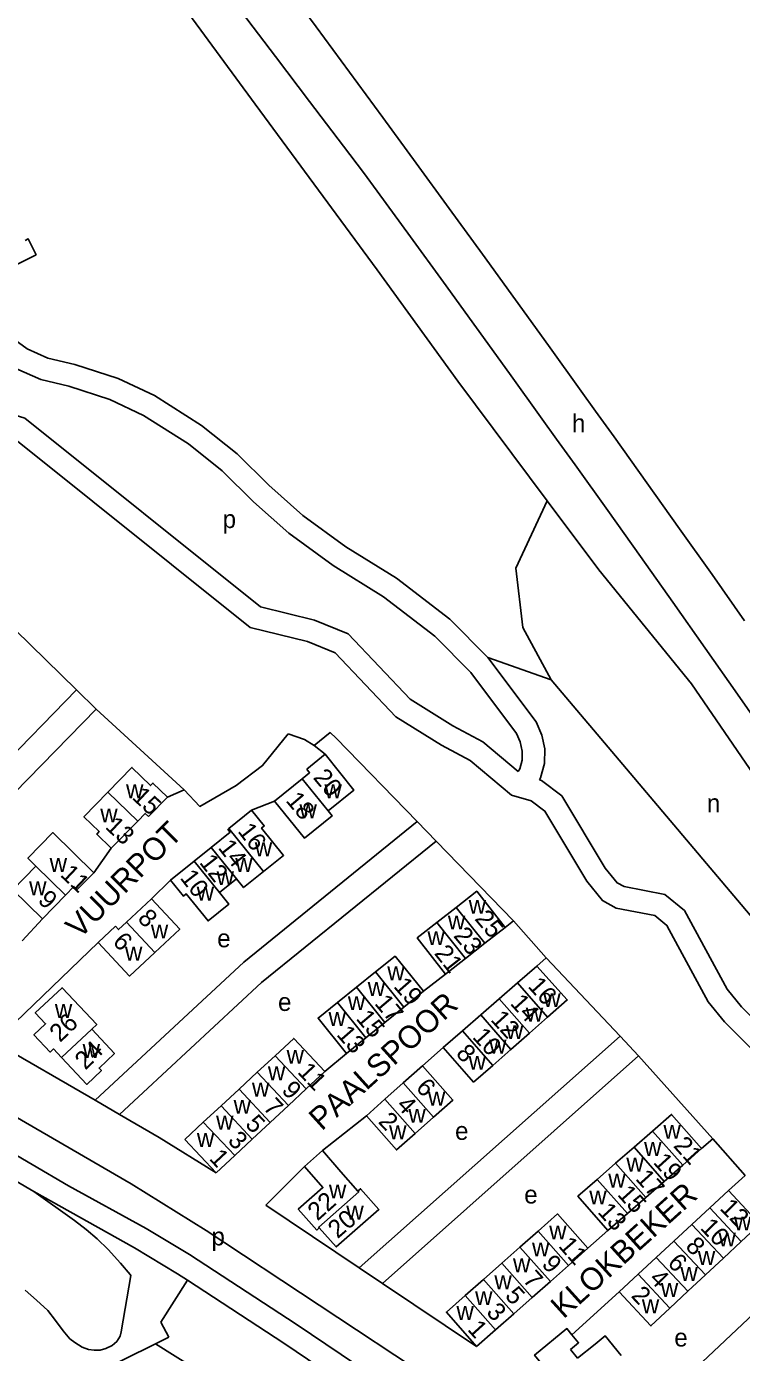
# Model space of a CAD drawing. Extents: x 159441 to 162086, y 388175 to 389787.
# Drawn here: x 161428.2 to 161586.8, y 389289.4 to 389583.7 of the extents above; entities that cross this region are included whole.
import ezdxf

# ---------------------------------------------------------------- set-up
doc = ezdxf.new("R2010")
doc.units = 0
for name, color, linetype in [('BLT_Basislijn', 7, 'Continuous'), ('BLT_Bebouwing', 7, 'Continuous'), ('BLT_Centroide', 7, 'Continuous'), ('BLT_Huisnummer', 7, 'Continuous'), ('BLT_Huisnummer_ tussenligend', 7, 'Continuous'), ('BLT_Onderverdeling_panden', 7, 'Continuous'), ('BLT_Straatnaam', 7, 'Continuous'), ('BLT_Vlakafsluiter', 7, 'Continuous')]:
    doc.layers.add(name, color=color, linetype=linetype)

msp = doc.modelspace()

# ---------------------------------------------------------------- linework, layer by layer
at = {"layer": 'BLT_Basislijn'}
for p, q in [((161383.9, 389379.42), (161439.23, 389436.44)), ((161443.62, 389432.16), (161439.23, 389436.44)), ((161443.62, 389432.16), (161463.1, 389414.22)), ((161486.17, 389426.67), (161489.82, 389425.44)), ((161491.95, 389424.06), (161494.43, 389422.14)), ((161459.41, 389412.61), (161463.1, 389414.22)), ((161478.09, 389409.72), (161483.16, 389411.76)), ((161519.05, 389402.87), (161514.85, 389407.19)), ((161536.2, 389385.19), (161519.05, 389402.87)), ((161443.08, 389395.85), (161446.94, 389401.27)), ((161455.9, 389390.05), (161460.13, 389394.19)), ((161427.19, 389380.73), (161431.71, 389385.62)), ((161536.2, 389385.19), (161534.34, 389383.72)), ((161536.2, 389385.19), (161543.45, 389376.98)), ((161421.08, 389358.27), (161444.06, 389380.35)), ((161516.21, 389369.53), (161521.13, 389373.34)), ((161501.97, 389308.16), (161559.82, 389359.6)), ((161563.93, 389355.23), (161559.82, 389359.6)), ((161494.31, 389351.71), (161499.17, 389355.75)), ((161507.11, 389304.7), (161563.93, 389355.23)), ((161520.62, 389357.04), (161516.01, 389353.01)), ((161443.36, 389345.36), (161448.79, 389342.21)), ((161448.79, 389342.21), (161457.6, 389337.11)), ((161503.56, 389341.9), (161493.84, 389334.19)), ((161580.41, 389336.8), (161587.55, 389328.63)), ((161489.81, 389330.62), (161481.24, 389322.1)), ((161587.55, 389328.63), (161583.88, 389325.3)), ((161481.24, 389322.1), (161501.97, 389308.16)), ((161557.15, 389316.42), (161552.71, 389312.5)), ((161501.97, 389308.16), (161507.11, 389304.7)), ((161457.93, 389296.13), (161463.86, 389305.42)), ((161507.11, 389304.7), (161527.98, 389290.67)), ((161559.63, 389302.82), (161549.16, 389293.32)), ((161456.75, 389291.27), (161491.3, 389269.76))]:
    msp.add_line(p, q, dxfattribs=at)
for points in [[(161543.69, 389478.37), (161523.86, 389504.93), (161505.95, 389529.67), (161478.86, 389566.44), (161457.19, 389596.01)], [(161485, 389593.68), (161492.42, 389583.62), (161499.82, 389573.54), (161507.21, 389563.46), (161514.58, 389553.36), (161521.94, 389543.26), (161529.28, 389533.14), (161536.61, 389523.01), (161543.92, 389512.88), (161551.22, 389502.73), (161554.39, 389498.31), (161558.51, 389492.57), (161565.77, 389482.39), (161573.01, 389472.2), (161580.24, 389462), (161587.44, 389451.78)], [(161475.82, 389586.9), (161483.4, 389576.97), (161490.96, 389567.04), (161498.51, 389557.1), (161502.92, 389551.28), (161505.98, 389547.09), (161513.33, 389537), (161520.66, 389526.89), (161527.98, 389516.78), (161535.28, 389506.65), (161542.57, 389496.52), (161545.74, 389492.1), (161549.84, 389486.37), (161557.1, 389476.21), (161564.33, 389466.04), (161571.54, 389455.86), (161578.73, 389445.66), (161585.9, 389435.44), (161593.05, 389425.21)], [(161427.86, 389536.18), (161428.54, 389536.51), (161430.3, 389532.99), (161421.26, 389528.53)], [(161530.5, 389443.58), (161522.03, 389452.09), (161510.21, 389461.22), (161498.99, 389468.19), (161489.49, 389475.11), (161481.93, 389481.84), (161474.86, 389488.78), (161466.99, 389495.13), (161456.52, 389501.73), (161448.47, 389505.52), (161438.87, 389508.66), (161432.92, 389510.04), (161428.28, 389512.12), (161419.52, 389518.47)], [(161537.21, 389418.33), (161537.56, 389418.92), (161538.1, 389420.8), (161538.12, 389422.8), (161537.68, 389424.86), (161536.85, 389426.77), (161526.71, 389440.3), (161518.71, 389448.33), (161507.35, 389457.11), (161496.2, 389464.04), (161486.35, 389471.21), (161478.52, 389478.19), (161471.53, 389485.04), (161464.07, 389491.06), (161454.11, 389497.34), (161446.62, 389500.86), (161437.52, 389503.84), (161431.31, 389505.28), (161425.76, 389507.77), (161421.81, 389510.63)], [(161537.21, 389418.33), (161529.36, 389424.91), (161522.71, 389428.48), (161513.29, 389434.38), (161499.5, 389448.87), (161492.04, 389451.92), (161480.04, 389454.84), (161427.81, 389496.7), (161417.81, 389499.83)], [(161589.54, 389356.14), (161583.02, 389362.73), (161579.4, 389367.2), (161570.22, 389384.16), (161567.55, 389386.32), (161558.99, 389388.01), (161555.9, 389389.68), (161552.43, 389393.96), (161543.15, 389409.51), (161540.12, 389411.79), (161535.71, 389413.06), (161526.54, 389420.75), (161520.2, 389424.16), (161510.11, 389430.47), (161496.62, 389444.64), (161490.49, 389447.15), (161477.78, 389450.24), (161425.41, 389492.21)], [(161544.52, 389438.64), (161538.25, 389450.28), (161536.73, 389463.42), (161543.69, 389478.37)], [(161864.11, 388992.72), (161862.26, 388996.22), (161834.62, 389043.66), (161820.58, 389066.73), (161794.96, 389108.1), (161778.03, 389134.85), (161748.78, 389180.87), (161736.01, 389200.14), (161730.36, 389208.82), (161706.15, 389245.56), (161679.72, 389284.71), (161666.51, 389304.75), (161627.77, 389361.67), (161610.82, 389386.7), (161592.22, 389413.57), (161575.68, 389437.79), (161555.14, 389463.04), (161543.69, 389478.37)], [(161439.23, 389436.44), (161422.15, 389453.11)], [(161541.93, 389416.47), (161542.19, 389416.9), (161543.1, 389420.07), (161543.13, 389423.31), (161542.46, 389426.39), (161541.21, 389429.3), (161530.5, 389443.58)], [(161819.53, 389045.68), (161815.48, 389052.86), (161784.08, 389105), (161747.27, 389163.43), (161708.15, 389220.33), (161663.36, 389280.15), (161636.73, 389321.37), (161599.17, 389374.01), (161561.24, 389418.87), (161544.52, 389438.64)], [(161389.22, 389376.43), (161443.62, 389432.16)], [(161463.1, 389414.22), (161466.63, 389410.56), (161474.67, 389415.22), (161480.53, 389419.61), (161486.17, 389426.67)], [(161491.95, 389424.06), (161489.82, 389425.44)], [(161514.85, 389407.19), (161496.86, 389425.73), (161495.53, 389426.95), (161491.95, 389424.06)], [(161665.94, 389267.22), (161644.27, 389297.16), (161632.06, 389317.53), (161628.84, 389320.63), (161616.45, 389326.78), (161614.95, 389328.05), (161612.91, 389331.22), (161603.71, 389347.88), (161598.07, 389353.27), (161593.31, 389359.44), (161586.75, 389366.07), (161583.57, 389369.99), (161574.14, 389387.43), (161569.73, 389390.99), (161560.7, 389392.77), (161559.16, 389393.6), (161556.54, 389396.83), (161546.94, 389412.91), (161542.39, 389416.34), (161541.93, 389416.47)], [(161443.36, 389345.36), (161476.39, 389376.03), (161514.85, 389407.19)], [(161448.79, 389342.21), (161480.32, 389371.49), (161519.05, 389402.87)], [(161543.45, 389376.98), (161541.34, 389375.11)], [(161559.82, 389359.6), (161543.45, 389376.98)], [(161421.08, 389358.27), (161443.36, 389345.36)], [(161580.41, 389336.8), (161563.93, 389355.23)], [(161411.85, 389349.75), (161451.41, 389326.83)], [(161437.49, 389326.37), (161405.15, 389345.27)], [(161429.8, 389325.08), (161400.53, 389342.18)], [(161457.6, 389337.11), (161470.24, 389329.22)], [(161577.92, 389334.61), (161580.41, 389336.8)], [(161429.8, 389325.08), (161438.83, 389318.69), (161441.42, 389316.65), (161443.82, 389314.56), (161446.24, 389312.21), (161449.02, 389309.2), (161451.15, 389306.66), (161451.31, 389306.44)], [(161429.8, 389325.08), (161452.09, 389312.58), (161461.65, 389306.86), (161463.86, 389305.42)], [(161437.49, 389326.37), (161454.67, 389316.87), (161464.3, 389311.1), (161488.01, 389295.63), (161511.38, 389279.86)], [(161451.41, 389326.83), (161468.04, 389316.44), (161518.16, 389283.27)], [(161557.27, 389269.87), (161573.01, 389282.52), (161603.38, 389311.15)], [(161427.9, 389303.23), (161430.39, 389300.98), (161432.88, 389298.66), (161434.6, 389296.49), (161436.31, 389294.17), (161437.77, 389292.43), (161438.87, 389291.56), (161440.52, 389290.58), (161441.92, 389290.05), (161443.16, 389289.88), (161444.51, 389289.91), (161445.77, 389290.23), (161447.17, 389290.89), (161448.18, 389291.8), (161448.9, 389292.97), (161449.18, 389293.93), (161451.31, 389306.44)], [(161463.86, 389305.42), (161485.25, 389291.46), (161506.5, 389277.12)], [(161457.93, 389296.13), (161459.75, 389292.75)], [(161459.75, 389292.75), (161456.75, 389291.27)], [(161456.75, 389291.27), (161436.02, 389281.03), (161437.12, 389278.67)]]:
    msp.add_lwpolyline(points, dxfattribs=at)
at = {"layer": 'BLT_Bebouwing'}
for p, q in [((161523.45, 389388.15), (161519.18, 389384.79)), ((161529.82, 389380.18), (161534.34, 389383.72)), ((161525.55, 389376.82), (161529.82, 389380.18)), ((161521.13, 389373.34), (161525.55, 389376.82)), ((161541.34, 389375.11), (161537.09, 389371.4)), ((161505.59, 389373.84), (161501.36, 389370.44)), ((161537.09, 389371.4), (161533.03, 389367.87)), ((161533.03, 389367.87), (161528.94, 389364.3)), ((161528.94, 389364.3), (161524.87, 389360.75)), ((161539.71, 389360.23), (161543.75, 389363.77)), ((161507.67, 389362.62), (161503.46, 389359.22)), ((161535.63, 389356.64), (161539.71, 389360.23)), ((161483.3, 389355.21), (161479.36, 389351.56)), ((161531.57, 389353.09), (161535.63, 389356.64)), ((161516.01, 389353.01), (161511.73, 389349.19)), ((161511.73, 389349.19), (161507.68, 389345.58)), ((161475.31, 389347.8), (161471.33, 389344.12)), ((161507.68, 389345.58), (161503.56, 389341.9)), ((161467.38, 389340.45), (161471.33, 389344.12)), ((161486.25, 389344.19), (161482.21, 389340.42)), ((161467.38, 389340.45), (161463.27, 389336.64)), ((161514.38, 389338), (161518.45, 389341.58)), ((161463.27, 389336.64), (161470.24, 389329.22)), ((161474.34, 389333.07), (161478.25, 389336.72)), ((161567.05, 389338.52), (161562.92, 389334.92)), ((161562.92, 389334.92), (161558.82, 389331.35)), ((161573.74, 389330.95), (161577.92, 389334.61)), ((161558.82, 389331.35), (161554.74, 389327.79)), ((161569.63, 389327.35), (161573.74, 389330.95)), ((161565.54, 389323.76), (161569.63, 389327.35)), ((161583.88, 389325.3), (161579.73, 389321.45)), ((161561.46, 389320.19), (161565.54, 389323.76)), ((161557.15, 389316.42), (161561.46, 389320.19)), ((161579.73, 389321.45), (161575.78, 389317.79)), ((161541.68, 389316.32), (161537.63, 389312.74)), ((161575.78, 389317.79), (161571.77, 389314.07)), ((161571.77, 389314.07), (161567.85, 389310.43)), ((161582.77, 389310.33), (161586.7, 389314.01)), ((161537.63, 389312.74), (161533.6, 389309.18)), ((161548.42, 389308.71), (161552.71, 389312.5)), ((161567.85, 389310.43), (161563.87, 389306.74)), ((161578.78, 389306.6), (161582.77, 389310.33)), ((161533.6, 389309.18), (161529.51, 389305.58)), ((161544.36, 389305.13), (161548.42, 389308.71)), ((161529.51, 389305.58), (161525.47, 389302.01)), ((161540.33, 389301.57), (161544.36, 389305.13)), ((161563.87, 389306.74), (161559.63, 389302.82)), ((161574.87, 389302.94), (161578.78, 389306.6)), ((161536.25, 389297.97), (161540.33, 389301.57)), ((161570.9, 389299.23), (161574.87, 389302.94)), ((161532.21, 389294.41), (161536.25, 389297.97)), ((161527.98, 389290.67), (161532.21, 389294.41)), ((161550.39, 389288.08), (161548.81, 389290))]:
    msp.add_line(p, q, dxfattribs=at)
for points in [[(161494.43, 389422.14), (161490.32, 389418.82)], [(161495.06, 389409.55), (161500.78, 389414.19), (161494.43, 389422.14)], [(161459.41, 389412.61), (161456.2, 389415.75), (161455.66, 389415.19), (161451.55, 389419.2), (161446.22, 389413.74)], [(161489.29, 389416.7), (161483.16, 389411.76)], [(161490.32, 389418.82), (161490.95, 389418.04), (161489.29, 389416.7)], [(161446.22, 389413.74), (161440.89, 389408.28), (161444.27, 389404.98), (161443.73, 389404.43), (161446.94, 389401.27)], [(161455.21, 389408.32), (161459.41, 389412.61)], [(161483.16, 389411.76), (161489.8, 389403.52), (161495.95, 389408.45), (161495.06, 389409.55)], [(161446.94, 389401.27), (161452.83, 389407.28)], [(161452.83, 389407.28), (161454.51, 389409), (161455.21, 389408.32)], [(161478.09, 389409.72), (161473.03, 389405.63)], [(161480.74, 389396.13), (161485.17, 389399.7), (161480.29, 389405.74), (161480.9, 389406.24), (161478.09, 389409.72)], [(161443.08, 389395.85), (161433.99, 389404.74), (161428.47, 389399.08), (161430.26, 389397.32)], [(161473.03, 389405.63), (161472.83, 389405.47), (161473.35, 389404.85), (161469.13, 389401.45)], [(161469.13, 389401.45), (161465.36, 389398.41)], [(161465.36, 389398.41), (161460.13, 389394.19)], [(161430.26, 389397.32), (161425.12, 389392.05), (161431.71, 389385.62)], [(161439.42, 389392.09), (161443.08, 389395.85)], [(161474.76, 389394.52), (161476.32, 389392.56), (161480.74, 389396.13)], [(161436.84, 389390.89), (161438.69, 389392.79), (161439.42, 389392.09)], [(161460.13, 389394.19), (161462.96, 389390.68), (161463.55, 389391.17), (161468.44, 389385.16), (161473.07, 389388.89), (161470.99, 389391.47)], [(161470.99, 389391.47), (161474.76, 389394.52)], [(161431.71, 389385.62), (161436.84, 389390.89)], [(161455.9, 389390.05), (161450.33, 389384.84)], [(161456.59, 389378.11), (161462.17, 389383.34), (161455.9, 389390.05)], [(161534.34, 389383.72), (161528.03, 389391.75), (161523.45, 389388.15)], [(161447.9, 389383.96), (161444.06, 389380.35)], [(161450.33, 389384.84), (161448.59, 389383.22), (161447.9, 389383.96)], [(161519.18, 389384.79), (161514.82, 389381.37), (161521.13, 389373.34)], [(161444.06, 389380.35), (161450.99, 389372.89), (161456.59, 389378.11)], [(161505.59, 389373.84), (161509.92, 389377.32), (161516.21, 389369.53)], [(161543.75, 389363.77), (161548.12, 389367.61), (161541.34, 389375.11)], [(161442.63, 389361.1), (161443.73, 389362.13), (161436.05, 389370.33), (161430.11, 389364.76), (161432.4, 389362.31), (161429.82, 389359.89), (161433.42, 389356.04), (161434.17, 389356.74), (161435.95, 389354.84)], [(161497.15, 389367.05), (161501.36, 389370.44)], [(161516.21, 389369.53), (161511.89, 389366.03)], [(161497.15, 389367.05), (161492.84, 389363.58), (161499.17, 389355.75)], [(161507.67, 389362.62), (161511.89, 389366.03)], [(161435.95, 389354.84), (161441.54, 389348.87), (161444.77, 389351.95), (161444.26, 389352.49), (161447.67, 389355.69), (161442.63, 389361.1)], [(161524.87, 389360.75), (161520.62, 389357.04)], [(161483.3, 389355.21), (161487.44, 389359.06), (161494.31, 389351.71)], [(161499.17, 389355.75), (161503.46, 389359.22)], [(161520.62, 389357.04), (161527.35, 389349.38), (161531.57, 389353.09)], [(161475.31, 389347.8), (161479.36, 389351.56)], [(161494.31, 389351.71), (161490.18, 389347.86)], [(161518.45, 389341.58), (161522.74, 389345.37), (161516.01, 389353.01)], [(161486.25, 389344.19), (161490.18, 389347.86)], [(161478.25, 389336.72), (161482.21, 389340.42)], [(161503.56, 389341.9), (161510.22, 389334.34), (161514.38, 389338)], [(161577.92, 389334.61), (161571.27, 389342.2), (161567.05, 389338.52)], [(161493.84, 389334.19), (161489.81, 389330.62)], [(161501.69, 389325.2), (161497.92, 389329.48), (161493.84, 389334.19)], [(161470.24, 389329.22), (161474.34, 389333.07)], [(161489.81, 389330.62), (161493.9, 389325.95), (161488.45, 389321.17), (161492.54, 389316.55), (161493.11, 389317.05)], [(161554.74, 389327.79), (161550.46, 389324.06), (161557.15, 389316.42)], [(161493.11, 389317.05), (161496.87, 389312.78), (161506.33, 389321.12), (161502.28, 389325.72), (161501.69, 389325.2)], [(161586.7, 389314.01), (161590.83, 389317.87), (161583.88, 389325.3)], [(161552.71, 389312.5), (161545.98, 389320.11), (161541.68, 389316.32)], [(161525.47, 389302.01), (161521.32, 389298.35), (161527.98, 389290.67)], [(161559.63, 389302.82), (161566.68, 389295.28), (161570.9, 389299.23)], [(161549.16, 389293.32), (161548.05, 389294.66), (161540.88, 389288.78), (161542.28, 389287.08)], [(161548.81, 389290), (161550.64, 389291.51), (161549.16, 389293.32)], [(161560.06, 389288.73), (161556.49, 389293.07), (161554.27, 389291.25), (161550.39, 389288.08)]]:
    msp.add_lwpolyline(points, dxfattribs=at)
at = {"layer": 'BLT_Onderverdeling_panden'}
for p, q in [((161523.45, 389388.15), (161529.82, 389380.18)), ((161519.18, 389384.79), (161525.55, 389376.82)), ((161511.89, 389366.03), (161505.59, 389373.84)), ((161501.36, 389370.44), (161507.67, 389362.62)), ((161537.09, 389371.4), (161543.75, 389363.77)), ((161503.46, 389359.22), (161497.15, 389367.05)), ((161533.03, 389367.87), (161539.71, 389360.23)), ((161528.94, 389364.3), (161535.63, 389356.64)), ((161524.87, 389360.75), (161531.57, 389353.09)), ((161490.18, 389347.86), (161483.3, 389355.21)), ((161479.36, 389351.56), (161486.25, 389344.19)), ((161511.73, 389349.19), (161518.45, 389341.58)), ((161482.21, 389340.42), (161475.31, 389347.8)), ((161507.68, 389345.58), (161514.38, 389338)), ((161471.33, 389344.12), (161478.25, 389336.72)), ((161474.34, 389333.07), (161467.38, 389340.45)), ((161567.05, 389338.52), (161573.74, 389330.95)), ((161562.92, 389334.92), (161569.63, 389327.35)), ((161558.82, 389331.35), (161565.54, 389323.76)), ((161554.74, 389327.79), (161561.46, 389320.19)), ((161579.73, 389321.45), (161586.7, 389314.01)), ((161541.68, 389316.32), (161548.42, 389308.71)), ((161575.78, 389317.79), (161582.77, 389310.33)), ((161571.77, 389314.07), (161578.78, 389306.6)), ((161537.63, 389312.74), (161544.36, 389305.13)), ((161567.85, 389310.43), (161574.87, 389302.94)), ((161533.6, 389309.18), (161540.33, 389301.57)), ((161529.51, 389305.58), (161536.25, 389297.97)), ((161563.87, 389306.74), (161570.9, 389299.23)), ((161525.47, 389302.01), (161532.21, 389294.41))]:
    msp.add_line(p, q, dxfattribs=at)
for points in [[(161495.06, 389409.55), (161489.29, 389416.7)], [(161452.83, 389407.28), (161446.22, 389413.74)], [(161480.74, 389396.13), (161473.03, 389405.63)], [(161474.76, 389394.52), (161469.13, 389401.45)], [(161470.99, 389391.47), (161465.36, 389398.41)], [(161430.26, 389397.32), (161436.84, 389390.89)], [(161456.59, 389378.11), (161450.33, 389384.84)], [(161442.63, 389361.1), (161435.95, 389354.84)], [(161501.69, 389325.2), (161501.85, 389325.03), (161492.97, 389317.2), (161493.11, 389317.05)]]:
    msp.add_lwpolyline(points, dxfattribs=at)
at = {"layer": 'BLT_Vlakafsluiter'}
msp.add_line((161544.52, 389438.64), (161530.5, 389443.58), dxfattribs=at)

# ---------------------------------------------------------------- texts
at = {"layer": 'BLT_Centroide'}
for s, p in [('h', (161549.15, 389493.6)), ('p', (161471.67, 389472.34)), ('w', (161450.24, 389412.39)), ('w', (161494.25, 389412.39)), ('w', (161488.71, 389407.95)), ('n', (161579.08, 389409.28)), ('w', (161444.52, 389407.01)), ('w', (161478.8, 389399.51)), ('w', (161433.29, 389396.01)), ('w', (161474.46, 389396.03)), ('w', (161470.32, 389393.09)), ('w', (161428.74, 389390.86)), ('w', (161465.91, 389389.68)), ('w', (161526.24, 389386.73)), ('w', (161455.74, 389381.27)), ('w', (161521.63, 389383.26)), ('e', (161470.46, 389379.3)), ('w', (161517.09, 389379.78)), ('w', (161450, 389376.33)), ('w', (161508.19, 389371.99)), ('w', (161503.85, 389368.51)), ('w', (161542.79, 389366.02)), ('w', (161434.45, 389363.64)), ('e', (161483.96, 389365.17)), ('w', (161499.44, 389365.37)), ('w', (161495.16, 389361.83)), ('w', (161538.92, 389362.81)), ('w', (161534.51, 389358.93)), ('w', (161440.6, 389354.75)), ('w', (161530.77, 389355.72)), ('w', (161485.85, 389353.46)), ('w', (161526.22, 389352.11)), ('w', (161481.71, 389349.78)), ('w', (161478.17, 389346.17)), ('w', (161474.1, 389342.36)), ('w', (161517.21, 389344.17)), ('w', (161512.87, 389340.36)), ('w', (161470.22, 389338.82)), ('w', (161508.59, 389336.68)), ('e', (161523.23, 389336.56)), ('w', (161569.45, 389336.79)), ('w', (161465.95, 389335)), ('w', (161565.16, 389332.98)), ('w', (161561.22, 389329.51)), ('w', (161557.21, 389325.96)), ('w', (161495.25, 389323.55)), ('e', (161538.57, 389322.43)), ('w', (161553, 389322.22)), ('w', (161499.1, 389318.85)), ('w', (161585.08, 389316.47)), ('p', (161469.19, 389313.13)), ('w', (161544.1, 389314.45)), ('w', (161581.66, 389312.89)), ('w', (161540.29, 389310.7)), ('w', (161536.08, 389307.16)), ('w', (161577.08, 389308.8)), ('w', (161573.21, 389305.25)), ('w', (161531.94, 389303.41)), ('w', (161568.87, 389301.7)), ('w', (161527.67, 389299.87)), ('w', (161523.53, 389296.59)), ('w', (161564.66, 389298.09)), ('e', (161571.86, 389290.69))]:
    msp.add_text(s, height=4, dxfattribs=at).set_placement(p)
at = {"layer": 'BLT_Huisnummer'}
for s, rotation, p in [('20', 309.9472, (161491.59, 389416.88)), ('15', 316.7983, (161451.36, 389412.4)), ('18', 310.0389, (161485.52, 389411.79)), ('13', 316.6587, (161445.43, 389405.83)), ('16', 307.9336, (161474.87, 389405.02)), ('14', 307.9447, (161470.5, 389401.36)), ('11', 316.748, (161435.46, 389395.21)), ('10', 308.0166, (161462.06, 389394.68)), ('9', 316.7406, (161430.47, 389389.5)), ('8', 314.0011, (161452.61, 389385.49)), ('25', 310.1707, (161527.42, 389385.54)), ('6', 314.1027, (161447.08, 389380.32)), ('21', 308.1707, (161518.46, 389377.91)), ('19', 311.1707, (161509.41, 389370.53)), ('16', 312.1707, (161539.2, 389370.54)), ('17', 310.1707, (161505.18, 389366.78)), ('26', 44.1707, (161435.61, 389358.03)), ('12', 312.1707, (161530.95, 389363.13)), ('13', 311.1707, (161496.77, 389359.84)), ('24', 44.1367, (161441.23, 389351.91)), ('8', 312.1707, (161523.23, 389355.59)), ('11', 313.1707, (161488.09, 389351.5)), ('9', 313.1707, (161484.56, 389347.4)), ('6', 313.1707, (161514.33, 389347.96)), ('2', 313.1707, (161506, 389340.46)), ('5', 313.1707, (161476.49, 389339.86)), ('21', 312.1707, (161571.48, 389335.13)), ('1', 313.1707, (161468.51, 389332.3)), ('17', 312.1707, (161563.06, 389327.85)), ('22', 41.7737, (161492.72, 389318.43)), ('13', 312.1707, (161554.68, 389320.44)), ('12', 314.1707, (161581.78, 389321.21)), ('20', 40.7737, (161497.17, 389314.5)), ('10', 314.1707, (161577.4, 389316.89)), ('11', 311.1707, (161545.98, 389312.93)), ('9', 312.1707, (161542.26, 389308.83)), ('6', 314.1707, (161570.15, 389309.04)), ('5', 312.1707, (161534.12, 389301.81)), ('2', 314.1707, (161562.08, 389301.8)), ('1', 312.1707, (161525.81, 389294.39))]:
    msp.add_text(s, height=4, rotation=rotation, dxfattribs=at).set_placement(p)
at = {"layer": 'BLT_Huisnummer_ tussenligend'}
for s, rotation, p in [('12', 307.9389, (161466.35, 389398.09)), ('23', 310.1707, (161522.71, 389381.77)), ('14', 312.1707, (161535.27, 389366.75)), ('15', 310.1707, (161501.09, 389363.4)), ('10', 312.1707, (161526.9, 389359.28)), ('7', 313.1707, (161480.48, 389343.57)), ('4', 313.1707, (161510.04, 389344.07)), ('3', 313.1707, (161472.61, 389336.23)), ('19', 312.1707, (161566.99, 389331.48)), ('15', 312.1707, (161559.04, 389324.34)), ('8', 314.1707, (161574.13, 389312.72)), ('7', 312.1707, (161538.09, 389305.35)), ('4', 314.1707, (161566.1, 389305.54)), ('3', 313.1707, (161529.97, 389298.15))]:
    msp.add_text(s, height=4, rotation=rotation, dxfattribs=at).set_placement(p)
at = {"layer": 'BLT_Straatnaam'}
for s, rotation, p in [('VUURPOT', 45.0628, (161439.92, 389380.99)), ('PAALSPOOR', 42.0628, (161493.63, 389338.41)), ('KLOKBEKER', 42.0628, (161547.28, 389296.68))]:
    msp.add_text(s, height=5, rotation=rotation, dxfattribs=at).set_placement(p)

doc.saveas('drawing.dxf')
